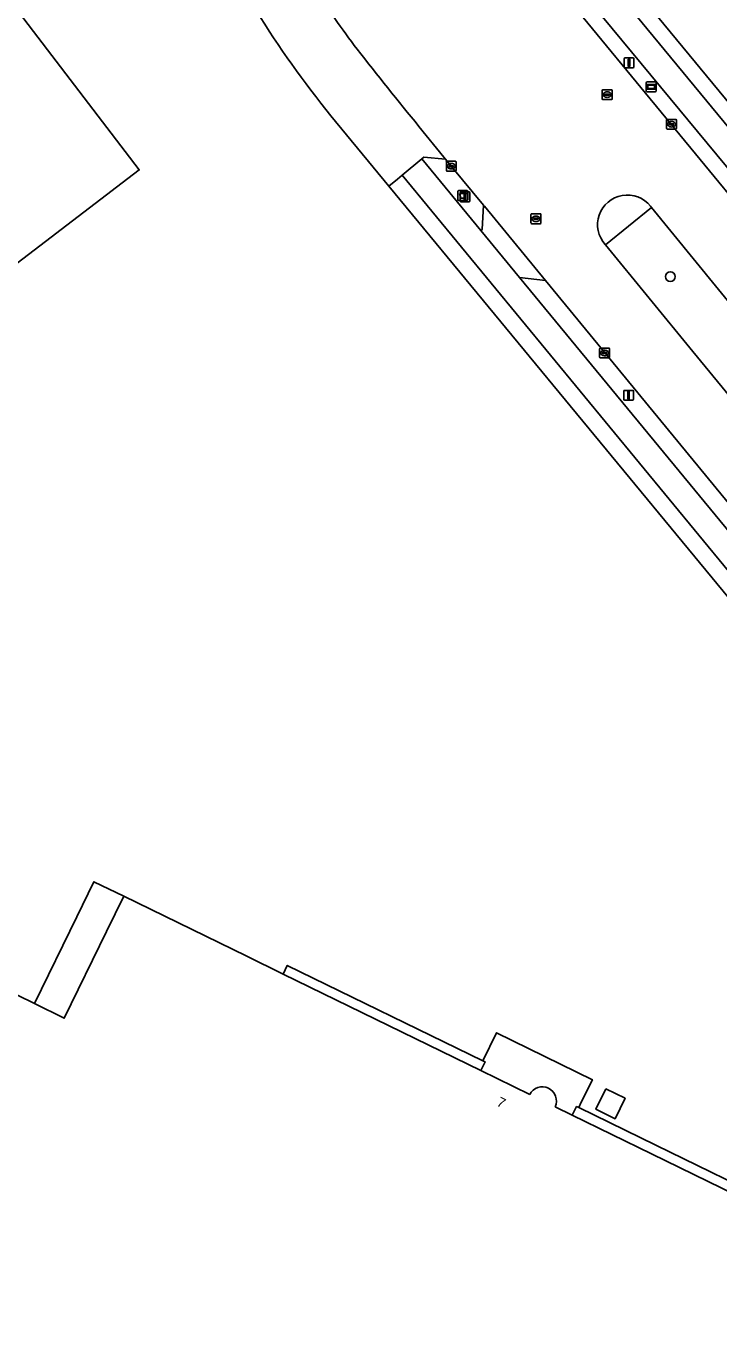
# Model space of a CAD drawing. Extents: x 156141 to 158132, y 385651 to 388333.
# Drawn here: x 156801.1 to 156871.2, y 386572.8 to 386704.3 of the extents above; entities that cross this region are included whole.
import ezdxf

# ---------------------------------------------------------------- set-up
doc = ezdxf.new("R2010")
doc.units = 0
for name, color, linetype in [('IMGEO_Afvalbak', 7, 'Continuous'), ('IMGEO_Berm_groen', 7, 'Continuous'), ('IMGEO_Boom', 7, 'Continuous'), ('IMGEO_Erf', 7, 'Continuous'), ('IMGEO_Fietspad_gesloten', 7, 'Continuous'), ('IMGEO_Kolk', 7, 'Continuous'), ('IMGEO_Lage_trafo', 7, 'Continuous'), ('IMGEO_Lichtmast', 7, 'Continuous'), ('IMGEO_Pand', 7, 'Continuous'), ('IMGEO_Pand_nummerreeks', 7, 'Continuous'), ('IMGEO_Pand_overbouw', 7, 'Continuous'), ('IMGEO_Rijbaan_lokaal_gesloten', 7, 'Continuous'), ('IMGEO_Rijbaan_lokaal_open', 7, 'Continuous'), ('IMGEO_Rioolput', 7, 'Continuous'), ('IMGEO_Verkeerseiland_gesloten', 7, 'Continuous'), ('IMGEO_Voetpad_op_trap', 7, 'Continuous'), ('IMGEO_Voetpad_open', 7, 'Continuous'), ('IMGEO_Wegwijzer', 7, 'Continuous')]:
    doc.layers.add(name, color=color, linetype=linetype)

msp = doc.modelspace()

# ---------------------------------------------------------------- linework, layer by layer
at = {"layer": 'IMGEO_Afvalbak'}
for p, q in [((156844.83, 386686.75), (156844.83, 386687.55)), ((156844.83, 386687.55), (156844.83, 386686.75)), ((156844.93, 386687.65), (156845.72, 386687.65)), ((156845.72, 386687.65), (156844.93, 386687.65)), ((156845.82, 386687.55), (156845.82, 386686.75)), ((156845.82, 386686.75), (156845.82, 386687.55)), ((156845.72, 386686.65), (156844.93, 386686.65)), ((156844.93, 386686.65), (156845.72, 386686.65))]:
    msp.add_line(p, q, dxfattribs=at)
msp.add_lwpolyline([(156844.98, 386687.37), (156845.68, 386687.37), (156845.53, 386686.9), (156845.12, 386686.9), (156844.98, 386687.37)], dxfattribs=at)
for centre, start, end in [((156844.93, 386687.55), 90, 180), ((156844.93, 386687.55), 90, 180), ((156845.72, 386687.55), 0, 90), ((156845.72, 386687.55), 360, 90), ((156844.93, 386686.75), 180, 270), ((156844.93, 386686.75), 180, 270), ((156845.72, 386686.75), 270, 0), ((156845.72, 386686.75), 270, 0)]:
    msp.add_arc(centre, 0.1, start, end, dxfattribs=at)
at = {"layer": 'IMGEO_Berm_groen'}
for points in [[(156855.44, 386707.7), (156899.02, 386654.79), (156903.83, 386648.96), (156905.07, 386649.89), (156902.1, 386653.51), (156902.22, 386653.62), (156900.19, 386656.06), (156856.53, 386708.8)], [(156873.15, 386675.26), (156864.42, 386685.93), (156859.76, 386682.16), (156868.58, 386671.36), (156906.63, 386625.11), (156920.65, 386608.13), (156928.2, 386598.95), (156933.33, 386592.72), (156946.24, 386577.02)]]:
    msp.add_lwpolyline(points, dxfattribs=at)
for points in [[(156844.16, 386690.12), (156843.56, 386690.84), (156841.37, 386691.02), (156841.17, 386690.86), (156847.15, 386683.6), (156847.28, 386683.7), (156847.43, 386686.17)], [(156853.68, 386678.56), (156851.06, 386678.85), (156937.51, 386573.96), (156942.96, 386567.34), (156954.38, 386553.46), (156961.99, 386544.22), (156981.71, 386520.27), (156981.81, 386520.36), (156981.89, 386522.72), (156969.99, 386537.17), (156967.69, 386539.97), (156963.32, 386545.25), (156955.67, 386554.54), (156954.39, 386556.06), (156950.45, 386560.89), (156944.25, 386568.41), (156938.82, 386574.99)]]:
    msp.add_lwpolyline(points, close=True, dxfattribs=at)
at = {"layer": 'IMGEO_Boom'}
msp.add_circle((156866.32, 386678.95), 0.489, dxfattribs=at)
at = {"layer": 'IMGEO_Erf'}
for points in [[(156745.51, 386753.92), (156745.65, 386753.97), (156747.06, 386752.22), (156751.05, 386755.26), (156750.97, 386755.69), (156760.83, 386757.52), (156761.14, 386757.1), (156763.61, 386753.87), (156770.5, 386744.82), (156770.83, 386745.09), (156773.57, 386741.52), (156773.3, 386741.28), (156774.55, 386739.62), (156776.92, 386741.4), (156777.23, 386741.01), (156774.82, 386739.2), (156812.59, 386689.74), (156789.57, 386672.17), (156756.89, 386714.98), (156712.28, 386681.03)], [(156858.96, 386712.66), (156903.23, 386658.99), (156908.93, 386652.06), (156913.25, 386655.62)], [(156837.85, 386688.1), (156831.96, 386695.23)], [(156934.05, 386571.56), (156837.85, 386688.1)], [(156755.29, 386532.42), (156793.03, 386609.78), (156801.99, 386605.4), (156806.26, 386614.17), (156808, 386617.73), (156811.03, 386616.25), (156823.4, 386610.22), (156827.16, 386608.38), (156847.15, 386598.62), (156847.58, 386599.51), (156847.35, 386599.62), (156848.73, 386602.44), (156858.43, 386597.69), (156857.31, 386595.42), (156857.05, 386594.88), (156856.84, 386594.98), (156856.4, 386594.11), (156864.43, 386590.19), (156881.48, 386581.86), (156890.86, 386577.29), (156902.2, 386571.76)]]:
    msp.add_lwpolyline(points, dxfattribs=at)
msp.add_lwpolyline([(156859.79, 386596.77), (156861.74, 386595.82), (156860.73, 386593.75), (156858.79, 386594.7)], close=True, dxfattribs=at)
msp.add_arc((156918.55, 386764.81), 111.08, 205.3323, 218.7835, dxfattribs=at)
at = {"layer": 'IMGEO_Fietspad_gesloten'}
msp.add_lwpolyline([(156856.53, 386708.8), (156900.19, 386656.06), (156902.22, 386653.62), (156904.22, 386655.24), (156902.08, 386657.85), (156858.04, 386711.23)], dxfattribs=at)
msp.add_lwpolyline([(156851.06, 386678.85), (156847.15, 386683.6), (156841.17, 386690.86), (156839.18, 386689.2), (156935.22, 386572.64), (156940.95, 386565.68), (156947.36, 386557.9), (156952.4, 386551.77), (156960.01, 386542.53), (156964.13, 386537.51), (156979.7, 386518.61), (156981.71, 386520.27), (156961.99, 386544.22), (156954.38, 386553.46), (156942.96, 386567.34), (156937.51, 386573.96)], close=True, dxfattribs=at)
at = {"layer": 'IMGEO_Kolk'}
for p, q in [((156865.94, 386693.94), (156865.94, 386694.79)), ((156866.02, 386694.86), (156866.87, 386694.86)), ((156866.87, 386693.86), (156866.02, 386693.86)), ((156866.2, 386694.36), (156866.2, 386694.37)), ((156866.24, 386694.41), (156866.64, 386694.41)), ((156866.64, 386694.32), (156866.24, 386694.32)), ((156866.43, 386694.64), (156866.45, 386694.64)), ((156866.45, 386694.08), (156866.43, 386694.08)), ((156866.68, 386694.37), (156866.68, 386694.36)), ((156866.94, 386694.79), (156866.94, 386693.94)), ((156843.66, 386689.69), (156843.66, 386690.54)), ((156843.73, 386690.62), (156844.58, 386690.62)), ((156844.58, 386689.62), (156843.73, 386689.62)), ((156843.91, 386690.11), (156843.91, 386690.12)), ((156844.35, 386690.07), (156843.95, 386690.07)), ((156843.96, 386690.16), (156844.36, 386690.16)), ((156844.14, 386690.4), (156844.17, 386690.4)), ((156844.17, 386689.84), (156844.14, 386689.84)), ((156844.4, 386690.12), (156844.4, 386690.11)), ((156844.66, 386690.54), (156844.66, 386689.69)), ((156859.17, 386670.79), (156859.17, 386671.65)), ((156859.24, 386671.72), (156860.1, 386671.72)), ((156859.43, 386671.21), (156859.43, 386671.23)), ((156859.47, 386671.26), (156859.87, 386671.26)), ((156859.66, 386671.5), (156859.68, 386671.5)), ((156859.91, 386671.23), (156859.91, 386671.21)), ((156860.17, 386671.65), (156860.17, 386670.79)), ((156860.1, 386670.72), (156859.24, 386670.72)), ((156859.87, 386671.18), (156859.47, 386671.18)), ((156859.68, 386670.94), (156859.66, 386670.94))]:
    msp.add_line(p, q, dxfattribs=at)
for points in [[(156865.94, 386693.94), (156865.94, 386694.79)], [(156866.02, 386694.86), (156866.87, 386694.86)], [(156866.87, 386693.86), (156866.02, 386693.86)], [(156866.94, 386694.79), (156866.94, 386693.94)], [(156843.66, 386689.69), (156843.66, 386690.54)], [(156843.73, 386690.62), (156844.58, 386690.62)], [(156844.58, 386689.62), (156843.73, 386689.62)], [(156844.66, 386690.54), (156844.66, 386689.69)], [(156859.17, 386670.79), (156859.17, 386671.65)], [(156859.24, 386671.72), (156860.1, 386671.72)], [(156860.17, 386671.65), (156860.17, 386670.79)], [(156860.1, 386670.72), (156859.24, 386670.72)]]:
    msp.add_lwpolyline(points, dxfattribs=at)
for centre, radius, start, end in [((156866.02, 386694.79), 0.0765, 91.552, 178.448), ((156866.02, 386694.79), 0.0765, 91.552, 178.448), ((156866.02, 386693.94), 0.0765, 181.552, 268.448), ((156866.02, 386693.94), 0.0765, 181.552, 268.448), ((156866.24, 386694.37), 0.0403, 85.8775, 175.7526), ((156866.24, 386694.36), 0.0366, 178.938, 274.7102), ((156866.65, 386694.37), 0.0386, 1.7309, 96.639), ((156866.64, 386694.36), 0.043, 264.8664, 352.4533), ((156866.87, 386694.79), 0.0765, 1.552, 88.448), ((156866.87, 386694.79), 0.0765, 1.552, 88.448), ((156866.87, 386693.94), 0.0765, 271.552, 358.448), ((156866.87, 386693.94), 0.0765, 271.552, 358.448), ((156843.73, 386690.54), 0.0765, 91.552, 178.448), ((156843.73, 386690.54), 0.0765, 91.552, 178.448), ((156843.73, 386689.69), 0.0765, 181.552, 268.448), ((156843.73, 386689.69), 0.0765, 181.552, 268.448), ((156843.96, 386690.12), 0.0403, 85.8775, 175.7526), ((156843.95, 386690.11), 0.0366, 178.938, 274.7102), ((156844.36, 386690.12), 0.043, 264.8664, 352.4533), ((156844.36, 386690.12), 0.0386, 1.7309, 96.639), ((156844.58, 386690.54), 0.0765, 1.552, 88.448), ((156844.58, 386690.54), 0.0765, 1.552, 88.448), ((156844.58, 386689.69), 0.0765, 271.552, 358.448), ((156844.58, 386689.69), 0.0765, 271.552, 358.448), ((156859.25, 386671.65), 0.0765, 91.552, 178.448), ((156859.25, 386671.65), 0.0765, 91.552, 178.448), ((156859.47, 386671.22), 0.0403, 85.8775, 175.7526), ((156859.47, 386671.21), 0.0366, 178.938, 274.7102), ((156859.87, 386671.23), 0.0386, 1.7309, 96.639), ((156859.87, 386671.22), 0.043, 264.8664, 352.4533), ((156860.09, 386671.65), 0.0765, 1.552, 88.448), ((156860.09, 386671.65), 0.0765, 1.552, 88.448), ((156859.25, 386670.8), 0.0765, 181.552, 268.448), ((156859.25, 386670.8), 0.0765, 181.552, 268.448), ((156860.09, 386670.8), 0.0765, 271.552, 358.448), ((156860.09, 386670.8), 0.0765, 271.552, 358.448)]:
    msp.add_arc(centre, radius, start, end, dxfattribs=at)
for centre, major_axis, ratio, start_param, end_param in [((156866.43, 386694.36), (-0.387, 0.002), 0.722429, 4.712389, 7.853982), ((156866.45, 386694.36), (-0.39, 0.002), 0.717154, 1.570796, 4.712389), ((156844.14, 386690.12), (-0.387, 0.002), 0.722429, 4.712389, 7.853982), ((156844.17, 386690.12), (-0.39, 0.002), 0.717154, 1.570796, 4.712389), ((156859.66, 386671.22), (-0.387, 0.002), 0.722429, 4.712389, 7.853982), ((156859.68, 386671.22), (-0.39, 0.002), 0.717154, 1.570796, 4.712389)]:
    msp.add_ellipse(centre, major_axis=major_axis, ratio=ratio, start_param=start_param, end_param=end_param, dxfattribs=at)
at = {"layer": 'IMGEO_Lage_trafo'}
msp.add_lwpolyline([(156859.79, 386596.77), (156858.79, 386594.7), (156860.73, 386593.75), (156861.74, 386595.82)], close=True, dxfattribs=at)
at = {"layer": 'IMGEO_Lichtmast'}
for p, q in [((156861.65, 386700.18), (156861.65, 386700.98)), ((156861.65, 386700.98), (156861.65, 386700.18)), ((156861.75, 386701.08), (156862.54, 386701.08)), ((156862.54, 386701.08), (156861.75, 386701.08)), ((156862.64, 386700.98), (156862.64, 386700.18)), ((156862.64, 386700.18), (156862.64, 386700.98)), ((156862.54, 386700.08), (156861.75, 386700.08)), ((156861.75, 386700.08), (156862.54, 386700.08)), ((156845.05, 386686.61), (156845.05, 386687.41)), ((156845.05, 386687.41), (156845.05, 386686.61)), ((156845.15, 386687.51), (156845.94, 386687.51)), ((156845.94, 386687.51), (156845.15, 386687.51)), ((156846.04, 386687.41), (156846.04, 386686.61)), ((156846.04, 386686.61), (156846.04, 386687.41)), ((156845.94, 386686.51), (156845.15, 386686.51)), ((156845.15, 386686.51), (156845.94, 386686.51)), ((156861.6, 386666.54), (156861.6, 386667.34)), ((156861.6, 386667.34), (156861.6, 386666.54)), ((156861.7, 386667.44), (156862.49, 386667.44)), ((156862.49, 386667.44), (156861.7, 386667.44)), ((156862.59, 386667.34), (156862.59, 386666.54)), ((156862.59, 386666.54), (156862.59, 386667.34)), ((156862.49, 386666.44), (156861.7, 386666.44)), ((156861.7, 386666.44), (156862.49, 386666.44))]:
    msp.add_line(p, q, dxfattribs=at)
for points in [[(156862.07, 386700.96), (156862.22, 386700.96), (156862.22, 386700.21), (156862.07, 386700.21), (156862.07, 386700.96)], [(156845.47, 386687.38), (156845.62, 386687.38), (156845.62, 386686.63), (156845.47, 386686.63), (156845.47, 386687.38)], [(156862.02, 386667.32), (156862.17, 386667.32), (156862.17, 386666.57), (156862.02, 386666.57), (156862.02, 386667.32)]]:
    msp.add_lwpolyline(points, dxfattribs=at)
for centre, start, end in [((156861.75, 386700.98), 90, 180), ((156861.75, 386700.98), 90, 180), ((156861.75, 386700.18), 180, 270), ((156861.75, 386700.18), 180, 270), ((156862.54, 386700.98), 0, 90), ((156862.54, 386700.98), 360, 90), ((156862.54, 386700.18), 270, 0), ((156862.54, 386700.18), 270, 0), ((156845.15, 386687.41), 90, 180), ((156845.15, 386687.41), 90, 180), ((156845.94, 386687.41), 0, 90), ((156845.94, 386687.41), 360, 90), ((156845.15, 386686.61), 180, 270), ((156845.15, 386686.61), 180, 270), ((156845.94, 386686.61), 270, 0), ((156845.94, 386686.61), 270, 0), ((156861.7, 386667.34), 90, 180), ((156861.7, 386667.34), 90, 180), ((156862.49, 386667.34), 0, 90), ((156862.49, 386667.34), 360, 90), ((156861.7, 386666.54), 180, 270), ((156861.7, 386666.54), 180, 270), ((156862.49, 386666.54), 270, 0), ((156862.49, 386666.54), 270, 0)]:
    msp.add_arc(centre, 0.1, start, end, dxfattribs=at)
at = {"layer": 'IMGEO_Pand'}
for points in [[(156701.97, 386689.8), (156704.26, 386691.55), (156712.28, 386681.03), (156756.89, 386714.98), (156789.57, 386672.17), (156812.59, 386689.74), (156774.82, 386739.2), (156777.23, 386741.01), (156776.92, 386741.4), (156774.55, 386739.62), (156773.3, 386741.28), (156773.57, 386741.52), (156770.83, 386745.09), (156770.5, 386744.82), (156763.61, 386753.87), (156761.14, 386757.1), (156760.83, 386757.52), (156750.97, 386755.69), (156751.05, 386755.26), (156747.06, 386752.22), (156745.65, 386753.97), (156745.51, 386753.92)], [(156852.1, 386596.21), (156847.15, 386598.62), (156827.16, 386608.38), (156823.4, 386610.22), (156811.03, 386616.25), (156809.29, 386612.69), (156805.01, 386603.92), (156801.99, 386605.4), (156793.03, 386609.78), (156755.29, 386532.42)], [(156941.81, 386537.18), (156921.59, 386547.04), (156915.66, 386549.94), (156914.03, 386550.73), (156915.27, 386553.27), (156914.59, 386553.61), (156913.35, 386551.07), (156905.93, 386554.69), (156907.17, 386557.24), (156906.49, 386557.57), (156905.24, 386555.02), (156896.19, 386559.44), (156902.2, 386571.76), (156890.86, 386577.29), (156881.48, 386581.86), (156864.43, 386590.19), (156856.4, 386594.11), (156854.67, 386594.95)]]:
    msp.add_lwpolyline(points, dxfattribs=at)
msp.add_arc((156853.37, 386595.55), 1.43, 335.348, 152.6121, dxfattribs=at)
at = {"layer": 'IMGEO_Pand_overbouw'}
for points in [[(156847.15, 386598.62), (156847.58, 386599.51), (156847.35, 386599.62), (156827.57, 386609.26), (156827.16, 386608.38)], [(156857.05, 386594.88), (156856.84, 386594.98), (156856.4, 386594.11), (156864.43, 386590.19), (156881.48, 386581.86), (156890.86, 386577.29), (156902.2, 386571.76), (156896.19, 386559.44), (156905.24, 386555.02), (156905.93, 386554.69), (156913.35, 386551.07), (156914.03, 386550.73), (156915.66, 386549.94), (156922.1, 386563.13), (156906.61, 386570.69), (156906.51, 386570.74), (156904.8, 386571.57), (156904.7, 386571.62), (156902.62, 386572.63), (156890.02, 386578.78), (156864.86, 386591.06)]]:
    msp.add_lwpolyline(points, close=True, dxfattribs=at)
at = {"layer": 'IMGEO_Rijbaan_lokaal_gesloten'}
for points in [[(156993.4, 386540.12), (156989.45, 386544.94), (156984.32, 386551.23), (156984.23, 386551.35), (156977.68, 386559.24), (156976.15, 386561.12), (156975.96, 386561.36), (156968.94, 386569.87), (156968, 386570.94), (156964.95, 386574.64), (156959.65, 386581.08), (156957.95, 386583.15), (156942.15, 386602.41), (156936.96, 386608.69), (156930.55, 386616.47), (156928.03, 386619.56), (156919.11, 386630.38), (156914.52, 386635.94), (156913.92, 386636.65), (156911.36, 386639.81), (156909.53, 386642), (156903.83, 386648.96), (156899.02, 386654.79), (156855.44, 386707.7)], [(156840.88, 386694.14), (156843.41, 386691.03), (156843.56, 386690.84), (156844.16, 386690.12), (156847.43, 386686.17), (156847.51, 386686.07), (156853.68, 386678.56), (156938.82, 386574.99), (156944.25, 386568.41), (156950.45, 386560.89), (156954.39, 386556.06), (156955.67, 386554.54), (156963.32, 386545.25), (156967.69, 386539.97), (156969.99, 386537.17), (156981.89, 386522.72), (156985.57, 386518.24), (156993.21, 386508.96)], [(156864.3, 386686.07), (156864.42, 386685.93), (156873.15, 386675.26), (156925.32, 386611.84)], [(156981.07, 386534.74), (156980.74, 386535.11), (156978.92, 386537.31), (156975.91, 386540.97), (156974.68, 386542.47), (156959.17, 386561.3), (156959.04, 386561.46), (156955.46, 386565.82), (156954.92, 386566.47), (156949.66, 386572.86), (156946.24, 386577.02), (156933.33, 386592.72), (156928.2, 386598.95), (156920.65, 386608.13), (156906.63, 386625.11), (156868.58, 386671.36), (156859.76, 386682.16), (156859.73, 386682.19)]]:
    msp.add_lwpolyline(points, dxfattribs=at)
for centre, radius, start, end in [((156979.73, 386810.4), 181.14, 214.3407, 216.7728), ((157169.5, 386963.5), 424.9, 217.9898, 219.3405), ((156861.96, 386684.2), 3, 38.565, 222.0504)]:
    msp.add_arc(centre, radius, start, end, dxfattribs=at)
at = {"layer": 'IMGEO_Rijbaan_lokaal_open'}
msp.add_lwpolyline([(156831.96, 386695.23), (156837.85, 386688.1), (156838.71, 386688.81), (156839.18, 386689.2), (156841.17, 386690.86), (156841.37, 386691.02), (156843.56, 386690.84), (156843.41, 386691.03), (156840.88, 386694.14)], dxfattribs=at)
msp.add_lwpolyline([(156847.51, 386686.07), (156847.43, 386686.17), (156847.28, 386683.7), (156847.15, 386683.6), (156851.06, 386678.85), (156853.68, 386678.56)], close=True, dxfattribs=at)
for centre, radius, start, end in [((156918.55, 386764.81), 111.08, 205.3323, 218.7835), ((156979.73, 386810.4), 181.14, 214.3407, 216.7728), ((157169.5, 386963.5), 424.9, 217.9898, 219.3405)]:
    msp.add_arc(centre, radius, start, end, dxfattribs=at)
at = {"layer": 'IMGEO_Rioolput'}
for p, q in [((156859.43, 386696.93), (156859.43, 386697.78)), ((156859.51, 386697.86), (156860.36, 386697.86)), ((156859.92, 386697.64), (156859.94, 386697.64)), ((156860.43, 386697.78), (156860.43, 386696.93)), ((156860.36, 386696.86), (156859.51, 386696.86)), ((156859.69, 386697.35), (156859.69, 386697.36)), ((156859.73, 386697.4), (156860.13, 386697.4)), ((156860.13, 386697.31), (156859.73, 386697.31)), ((156859.94, 386697.08), (156859.92, 386697.08)), ((156860.17, 386697.36), (156860.17, 386697.35)), ((156852.22, 386684.38), (156852.22, 386685.23)), ((156852.3, 386685.3), (156853.15, 386685.3)), ((156852.48, 386684.8), (156852.48, 386684.81)), ((156852.52, 386684.85), (156852.92, 386684.85)), ((156852.92, 386684.76), (156852.52, 386684.76)), ((156852.71, 386685.08), (156852.73, 386685.08)), ((156852.73, 386684.52), (156852.71, 386684.52)), ((156852.96, 386684.81), (156852.96, 386684.8)), ((156853.22, 386685.23), (156853.22, 386684.38)), ((156853.15, 386684.3), (156852.3, 386684.3))]:
    msp.add_line(p, q, dxfattribs=at)
for points in [[(156859.43, 386696.93), (156859.43, 386697.78)], [(156859.51, 386697.86), (156860.36, 386697.86)], [(156860.43, 386697.78), (156860.43, 386696.93)], [(156860.36, 386696.86), (156859.51, 386696.86)], [(156852.22, 386684.38), (156852.22, 386685.23)], [(156852.3, 386685.3), (156853.15, 386685.3)], [(156853.22, 386685.23), (156853.22, 386684.38)], [(156853.15, 386684.3), (156852.3, 386684.3)]]:
    msp.add_lwpolyline(points, dxfattribs=at)
for centre, radius, start, end in [((156859.51, 386697.78), 0.0765, 91.552, 178.448), ((156859.51, 386697.78), 0.0765, 91.552, 178.448), ((156860.36, 386697.78), 0.0765, 1.552, 88.448), ((156860.36, 386697.78), 0.0765, 1.552, 88.448), ((156859.51, 386696.93), 0.0765, 181.552, 268.448), ((156859.51, 386696.93), 0.0765, 181.552, 268.448), ((156859.73, 386697.36), 0.0403, 85.8775, 175.7526), ((156859.73, 386697.35), 0.0366, 178.938, 274.7102), ((156860.14, 386697.36), 0.0386, 1.7309, 96.639), ((156860.13, 386697.36), 0.043, 264.8664, 352.4533), ((156860.36, 386696.93), 0.0765, 271.552, 358.448), ((156860.36, 386696.93), 0.0765, 271.552, 358.448), ((156852.3, 386685.23), 0.0765, 91.552, 178.448), ((156852.3, 386685.23), 0.0765, 91.552, 178.448), ((156852.3, 386684.38), 0.0765, 181.552, 268.448), ((156852.3, 386684.38), 0.0765, 181.552, 268.448), ((156852.52, 386684.81), 0.0403, 85.8775, 175.7526), ((156852.52, 386684.8), 0.0366, 178.938, 274.7102), ((156852.93, 386684.81), 0.0386, 1.7309, 96.639), ((156852.92, 386684.8), 0.043, 264.8664, 352.4533), ((156853.15, 386685.23), 0.0765, 1.552, 88.448), ((156853.15, 386685.23), 0.0765, 1.552, 88.448), ((156853.15, 386684.38), 0.0765, 271.552, 358.448), ((156853.15, 386684.38), 0.0765, 271.552, 358.448)]:
    msp.add_arc(centre, radius, start, end, dxfattribs=at)
for centre, major_axis, ratio, start_param, end_param in [((156859.92, 386697.36), (-0.387, 0.002), 0.722429, 4.712389, 7.853982), ((156859.94, 386697.36), (-0.39, 0.002), 0.717154, 1.570796, 4.712389), ((156852.71, 386684.8), (-0.387, 0.002), 0.722429, 4.712389, 7.853982), ((156852.73, 386684.8), (-0.39, 0.002), 0.717154, 1.570796, 4.712389)]:
    msp.add_ellipse(centre, major_axis=major_axis, ratio=ratio, start_param=start_param, end_param=end_param, dxfattribs=at)
at = {"layer": 'IMGEO_Verkeerseiland_gesloten'}
for points in [[(156859.73, 386682.19), (156859.76, 386682.16), (156864.42, 386685.93)], [(156864.42, 386685.93), (156864.3, 386686.07)]]:
    msp.add_lwpolyline(points, dxfattribs=at)
msp.add_arc((156861.96, 386684.2), 3, 38.565, 222.0504, dxfattribs=at)
at = {"layer": 'IMGEO_Voetpad_op_trap'}
msp.add_lwpolyline([(156811.03, 386616.25), (156808, 386617.73), (156806.26, 386614.17), (156801.99, 386605.4), (156805.01, 386603.92), (156809.29, 386612.69)], close=True, dxfattribs=at)
for points in [[(156848.73, 386602.44), (156847.35, 386599.62), (156847.58, 386599.51), (156847.15, 386598.62), (156852.1, 386596.21)], [(156854.67, 386594.95), (156856.4, 386594.11), (156856.84, 386594.98), (156857.05, 386594.88), (156857.31, 386595.42), (156858.43, 386597.69), (156848.73, 386602.44)]]:
    msp.add_lwpolyline(points, dxfattribs=at)
msp.add_arc((156853.37, 386595.55), 1.43, 335.348, 152.6121, dxfattribs=at)
at = {"layer": 'IMGEO_Voetpad_open'}
msp.add_lwpolyline([(156858.04, 386711.23), (156902.08, 386657.85), (156904.22, 386655.24), (156907.2, 386651.63), (156907.93, 386650.74), (156909.16, 386651.78), (156908.93, 386652.06), (156903.23, 386658.99), (156858.96, 386712.66)], dxfattribs=at)
msp.add_lwpolyline([(156839.18, 386689.2), (156838.71, 386688.81), (156837.85, 386688.1), (156934.05, 386571.56), (156944.36, 386559.04), (156951.16, 386550.77), (156952.4, 386551.77), (156947.36, 386557.9), (156940.95, 386565.68), (156935.22, 386572.64)], close=True, dxfattribs=at)
at = {"layer": 'IMGEO_Wegwijzer'}
for p, q in [((156863.89, 386697.75), (156863.89, 386698.55)), ((156863.89, 386698.55), (156863.89, 386697.75)), ((156863.99, 386698.65), (156864.78, 386698.65)), ((156864.78, 386698.65), (156863.99, 386698.65)), ((156864.78, 386697.65), (156863.99, 386697.65)), ((156863.99, 386697.65), (156864.78, 386697.65)), ((156864.88, 386698.55), (156864.88, 386697.75)), ((156864.88, 386697.75), (156864.88, 386698.55))]:
    msp.add_line(p, q, dxfattribs=at)
for points in [[(156863.99, 386698.38), (156864.77, 386698.38), (156864.77, 386697.92), (156863.99, 386697.92), (156863.99, 386698.38)], [(156864.05, 386698.32), (156864.05, 386697.98), (156864.71, 386697.98), (156864.71, 386698.32), (156864.05, 386698.32)]]:
    msp.add_lwpolyline(points, dxfattribs=at)
for centre, start, end in [((156863.99, 386698.55), 90, 180), ((156863.99, 386698.55), 90, 180), ((156863.99, 386697.75), 180, 270), ((156863.99, 386697.75), 180, 270), ((156864.78, 386698.55), 0, 90), ((156864.78, 386698.55), 360, 90), ((156864.78, 386697.75), 270, 0), ((156864.78, 386697.75), 270, 0)]:
    msp.add_arc(centre, 0.1, start, end, dxfattribs=at)

# ---------------------------------------------------------------- texts
at = {"layer": 'IMGEO_Pand_nummerreeks'}
msp.add_text('7', height=1, rotation=333.7815, dxfattribs=at).set_placement((156848.67, 386595.1))

doc.saveas('drawing.dxf')
